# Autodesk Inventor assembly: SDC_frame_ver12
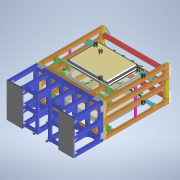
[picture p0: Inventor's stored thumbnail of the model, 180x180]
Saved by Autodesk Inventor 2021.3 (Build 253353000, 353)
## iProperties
Created: 2022-02
Part Number: SDC_frame_ver12
Document SubType Name: Assembly
Designer: kengo
Author: kengo
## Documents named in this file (13)
- C:\Users\kengo\Documents\frame_misumi_ver12\SDC_frame_ver12.iam
- C:\Users\kengo\Documents\frame_misumi_ver12\SDC_frame_arm_12.iam
- C:\Users\kengo\Documents\frame_misumi_ver12\SDC_frame_leg_12.iam
- C:\Users\kengo\Documents\frame_misumi_ver12\HBLFSDW8-90-SET_tuika.iam
- C:\Users\kengo\Documents\frame_misumi_ver12\JTAC-SET.iam
- C:\Users\kengo\Documents\frame_misumi_ver12\upper-stage\SDC345_up_stage.iam
- C:\Users\kengo\Documents\frame_misumi_ver12\upper-stage\SDC345_up_stage_mirror.iam
- C:\Users\kengo\Documents\frame_misumi_ver12\stage\SDC345_down_stage.iam
- C:\Users\kengo\Documents\frame_misumi_ver12\stage\SDC345_down_stage_mirror.iam
- C:\Users\kengo\Documents\frame_misumi_ver12\Anker\foot\SDC_foot_ver9.iam
- C:\Users\kengo\Documents\frame_misumi_ver12\IBolt\Ibolt_set.iam
- C:\Users\kengo\Documents\frame_misumi_ver12\SDC13301330\SDC_E70_assembly.iam
- C:\Users\kengo\Documents\frame_misumi_ver12\SDCsmallY\SDC_smallY.ipt
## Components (39 placed, 12 different names)
1. SDC_frame_arm_12:1 [sub-assembly] — メイト:1, フラッシュ:1, フラッシュ:2, メイト:29, メイト:31, メイト:33, メイト:35, メイト:37, メイト:39, メイト:41, メイト:43, メイト:44, フラッシュ:55, メイト:45, フラッシュ:57, メイト:46, フラッシュ:59, メイト:47, フラッシュ:61, メイト:48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
2. SDC_frame_leg_12:1 [sub-assembly] — メイト:1, フラッシュ:1, フラッシュ:2, メイト:28, フラッシュ:46, メイト:30, フラッシュ:47, メイト:32, フラッシュ:48, メイト:34, フラッシュ:49, メイト:36, フラッシュ:50, メイト:38, フラッシュ:51, メイト:40, フラッシュ:52, メイト:42, フラッシュ:53, フラッシュ:54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
3. HBLFSDW8-90-SET_tuika:1 [sub-assembly] — メイト:34, メイト:35, フラッシュ:49
4. HBLFSDW8-90-SET_tuika:2 [sub-assembly] — メイト:30, メイト:31, フラッシュ:47
5. HBLFSDW8-90-SET_tuika:3 [sub-assembly] — メイト:28, メイト:29, フラッシュ:46
6. HBLFSDW8-90-SET_tuika:4 [sub-assembly] — メイト:32, メイト:33, フラッシュ:48
7. HBLFSDW8-90-SET_tuika:5 [sub-assembly] — メイト:40, メイト:41, フラッシュ:52
8. HBLFSDW8-90-SET_tuika:6 [sub-assembly] — メイト:42, メイト:43, フラッシュ:53
9. HBLFSDW8-90-SET_tuika:7 [sub-assembly] — メイト:36, メイト:37, フラッシュ:50
10. HBLFSDW8-90-SET_tuika:8 [sub-assembly] — メイト:38, メイト:39, フラッシュ:51
11. JTAC-SET:1 [sub-assembly] — メイト:46, フラッシュ:58, フラッシュ:59
12. JTAC-SET:2 [sub-assembly] — メイト:47, フラッシュ:60, フラッシュ:61
13. JTAC-SET:3 [sub-assembly] — メイト:45, フラッシュ:56, フラッシュ:57
14. JTAC-SET:4 [sub-assembly] — メイト:44, フラッシュ:54, フラッシュ:55
15. JTAC-SET:5 [sub-assembly] — メイト:51, フラッシュ:68, フラッシュ:69
16. JTAC-SET:6 [sub-assembly] — メイト:50, フラッシュ:66, フラッシュ:67
17. JTAC-SET:7 [sub-assembly] — メイト:49, フラッシュ:64, フラッシュ:65
18. JTAC-SET:8 [sub-assembly] — メイト:48, フラッシュ:62, フラッシュ:63
19. SDC345_up_stage:1 [sub-assembly] — メイト:54, フラッシュ:74, フラッシュ:75
20. SDC345_up_stage:2 [sub-assembly] — メイト:53, フラッシュ:72, フラッシュ:73
21. SDC345_up_stage:3 [sub-assembly] — メイト:52, フラッシュ:70, フラッシュ:71
22. SDC345_up_stage_mirror:1 [sub-assembly] — メイト:56, フラッシュ:78, フラッシュ:79
23. SDC345_up_stage_mirror:2 [sub-assembly] — メイト:55, フラッシュ:76, フラッシュ:77
24. SDC345_up_stage_mirror:3 [sub-assembly] — メイト:57, フラッシュ:80, フラッシュ:81
25. SDC345_down_stage:1 [sub-assembly] — メイト:58, フラッシュ:82, フラッシュ:83, メイト:74
26. SDC345_down_stage:2 [sub-assembly] — メイト:59, フラッシュ:84, フラッシュ:85
27. SDC345_down_stage:3 [sub-assembly] — メイト:60, フラッシュ:86, フラッシュ:87
28. SDC345_down_stage_mirror:1 [sub-assembly] — メイト:61, フラッシュ:88, フラッシュ:89
29. SDC345_down_stage_mirror:2 [sub-assembly] — メイト:63, フラッシュ:92, フラッシュ:93, メイト:72
30. SDC345_down_stage_mirror:3 [sub-assembly] — メイト:62, フラッシュ:90, フラッシュ:91, メイト:70
31. SDC_foot_ver9:1 [sub-assembly] — メイト:64, フラッシュ:94, フラッシュ:95
32. SDC_foot_ver9:2 [sub-assembly] — メイト:65, フラッシュ:96, フラッシュ:97
33. Ibolt_set:1 [sub-assembly] — メイト:68, フラッシュ:102, フラッシュ:103
34. Ibolt_set:2 [sub-assembly] — メイト:66, フラッシュ:98, フラッシュ:99
35. Ibolt_set:3 [sub-assembly] — メイト:67, フラッシュ:100, フラッシュ:101
36. Ibolt_set:4 [sub-assembly] — メイト:69, フラッシュ:104, フラッシュ:105
37. SDC_E70_assembly:1 [sub-assembly] — メイト:70, フラッシュ:106, メイト:71
38. SDC_E70_assembly:2 [sub-assembly] — メイト:72, フラッシュ:107, メイト:73
39. SDC_smallY:1 — メイト:74, フラッシュ:108, メイト:75
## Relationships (114: Flush 65, Mate 49)
- メイト:1 [Mate]: SDC_frame_arm_12:1 ↔ SDC_frame_leg_12:1
- フラッシュ:1 [Flush]: SDC_frame_arm_12:1 ↔ SDC_frame_leg_12:1
- フラッシュ:2 [Flush]: SDC_frame_arm_12:1 ↔ SDC_frame_leg_12:1
- メイト:28 [Mate]: SDC_frame_leg_12:1 ↔ HBLFSDW8-90-SET_tuika:3
- メイト:29 [Mate]: SDC_frame_arm_12:1 ↔ HBLFSDW8-90-SET_tuika:3
- フラッシュ:46 [Flush]: SDC_frame_leg_12:1 ↔ HBLFSDW8-90-SET_tuika:3
- メイト:30 [Mate]: SDC_frame_leg_12:1 ↔ HBLFSDW8-90-SET_tuika:2
- メイト:31 [Mate]: SDC_frame_arm_12:1 ↔ HBLFSDW8-90-SET_tuika:2
- フラッシュ:47 [Flush]: SDC_frame_leg_12:1 ↔ HBLFSDW8-90-SET_tuika:2
- メイト:32 [Mate]: SDC_frame_leg_12:1 ↔ HBLFSDW8-90-SET_tuika:4
- メイト:33 [Mate]: SDC_frame_arm_12:1 ↔ HBLFSDW8-90-SET_tuika:4
- フラッシュ:48 [Flush]: SDC_frame_leg_12:1 ↔ HBLFSDW8-90-SET_tuika:4
- メイト:34 [Mate]: SDC_frame_leg_12:1 ↔ HBLFSDW8-90-SET_tuika:1
- メイト:35 [Mate]: SDC_frame_arm_12:1 ↔ HBLFSDW8-90-SET_tuika:1
- フラッシュ:49 [Flush]: SDC_frame_leg_12:1 ↔ HBLFSDW8-90-SET_tuika:1
- メイト:36 [Mate]: SDC_frame_leg_12:1 ↔ HBLFSDW8-90-SET_tuika:7
- メイト:37 [Mate]: SDC_frame_arm_12:1 ↔ HBLFSDW8-90-SET_tuika:7
- フラッシュ:50 [Flush]: SDC_frame_leg_12:1 ↔ HBLFSDW8-90-SET_tuika:7
- メイト:38 [Mate]: SDC_frame_leg_12:1 ↔ HBLFSDW8-90-SET_tuika:8
- メイト:39 [Mate]: SDC_frame_arm_12:1 ↔ HBLFSDW8-90-SET_tuika:8
- フラッシュ:51 [Flush]: SDC_frame_leg_12:1 ↔ HBLFSDW8-90-SET_tuika:8
- メイト:40 [Mate]: SDC_frame_leg_12:1 ↔ HBLFSDW8-90-SET_tuika:5
- メイト:41 [Mate]: SDC_frame_arm_12:1 ↔ HBLFSDW8-90-SET_tuika:5
- フラッシュ:52 [Flush]: SDC_frame_leg_12:1 ↔ HBLFSDW8-90-SET_tuika:5
- メイト:42 [Mate]: SDC_frame_leg_12:1 ↔ HBLFSDW8-90-SET_tuika:6
- メイト:43 [Mate]: SDC_frame_arm_12:1 ↔ HBLFSDW8-90-SET_tuika:6
- フラッシュ:53 [Flush]: SDC_frame_leg_12:1 ↔ HBLFSDW8-90-SET_tuika:6
- メイト:44 [Mate]: SDC_frame_arm_12:1 ↔ JTAC-SET:4
- フラッシュ:54 [Flush]: SDC_frame_leg_12:1 ↔ JTAC-SET:4
- フラッシュ:55 [Flush]: SDC_frame_arm_12:1 ↔ JTAC-SET:4
- メイト:45 [Mate]: SDC_frame_arm_12:1 ↔ JTAC-SET:3
- フラッシュ:56 [Flush]: SDC_frame_leg_12:1 ↔ JTAC-SET:3
- フラッシュ:57 [Flush]: SDC_frame_arm_12:1 ↔ JTAC-SET:3
- メイト:46 [Mate]: SDC_frame_arm_12:1 ↔ JTAC-SET:1
- フラッシュ:58 [Flush]: SDC_frame_leg_12:1 ↔ JTAC-SET:1
- フラッシュ:59 [Flush]: SDC_frame_arm_12:1 ↔ JTAC-SET:1
- メイト:47 [Mate]: SDC_frame_arm_12:1 ↔ JTAC-SET:2
- フラッシュ:60 [Flush]: SDC_frame_leg_12:1 ↔ JTAC-SET:2
- フラッシュ:61 [Flush]: SDC_frame_arm_12:1 ↔ JTAC-SET:2
- メイト:48 [Mate]: SDC_frame_arm_12:1 ↔ JTAC-SET:8
- フラッシュ:62 [Flush]: SDC_frame_leg_12:1 ↔ JTAC-SET:8
- フラッシュ:63 [Flush]: SDC_frame_leg_12:1 ↔ JTAC-SET:8
- メイト:49 [Mate]: SDC_frame_arm_12:1 ↔ JTAC-SET:7
- フラッシュ:64 [Flush]: SDC_frame_leg_12:1 ↔ JTAC-SET:7
- フラッシュ:65 [Flush]: SDC_frame_leg_12:1 ↔ JTAC-SET:7
- メイト:50 [Mate]: SDC_frame_arm_12:1 ↔ JTAC-SET:6
- フラッシュ:66 [Flush]: SDC_frame_leg_12:1 ↔ JTAC-SET:6
- フラッシュ:67 [Flush]: SDC_frame_leg_12:1 ↔ JTAC-SET:6
- メイト:51 [Mate]: SDC_frame_arm_12:1 ↔ JTAC-SET:5
- フラッシュ:68 [Flush]: SDC_frame_leg_12:1 ↔ JTAC-SET:5
- フラッシュ:69 [Flush]: SDC_frame_leg_12:1 ↔ JTAC-SET:5
- メイト:52 [Mate]: SDC_frame_arm_12:1 ↔ SDC345_up_stage:3
- フラッシュ:70 [Flush]: SDC_frame_arm_12:1 ↔ SDC345_up_stage:3
- フラッシュ:71 [Flush]: SDC_frame_arm_12:1 ↔ SDC345_up_stage:3
- メイト:53 [Mate]: SDC_frame_arm_12:1 ↔ SDC345_up_stage:2
- フラッシュ:72 [Flush]: SDC_frame_arm_12:1 ↔ SDC345_up_stage:2
- フラッシュ:73 [Flush]: SDC_frame_arm_12:1 ↔ SDC345_up_stage:2
- メイト:54 [Mate]: SDC_frame_arm_12:1 ↔ SDC345_up_stage:1
- フラッシュ:74 [Flush]: SDC_frame_arm_12:1 ↔ SDC345_up_stage:1
- フラッシュ:75 [Flush]: SDC_frame_arm_12:1 ↔ SDC345_up_stage:1
- メイト:55 [Mate]: SDC_frame_arm_12:1 ↔ SDC345_up_stage_mirror:2
- フラッシュ:76 [Flush]: SDC_frame_arm_12:1 ↔ SDC345_up_stage_mirror:2
- フラッシュ:77 [Flush]: SDC_frame_arm_12:1 ↔ SDC345_up_stage_mirror:2
- メイト:56 [Mate]: SDC_frame_arm_12:1 ↔ SDC345_up_stage_mirror:1
- フラッシュ:78 [Flush]: SDC_frame_arm_12:1 ↔ SDC345_up_stage_mirror:1
- フラッシュ:79 [Flush]: SDC_frame_arm_12:1 ↔ SDC345_up_stage_mirror:1
- メイト:57 [Mate]: SDC_frame_arm_12:1 ↔ SDC345_up_stage_mirror:3
- フラッシュ:80 [Flush]: SDC_frame_arm_12:1 ↔ SDC345_up_stage_mirror:3
- フラッシュ:81 [Flush]: SDC_frame_arm_12:1 ↔ SDC345_up_stage_mirror:3
- メイト:58 [Mate]: SDC_frame_arm_12:1 ↔ SDC345_down_stage:1
- フラッシュ:82 [Flush]: SDC_frame_arm_12:1 ↔ SDC345_down_stage:1
- フラッシュ:83 [Flush]: SDC_frame_arm_12:1 ↔ SDC345_down_stage:1
- メイト:59 [Mate]: SDC_frame_arm_12:1 ↔ SDC345_down_stage:2
- フラッシュ:84 [Flush]: SDC_frame_arm_12:1 ↔ SDC345_down_stage:2
- フラッシュ:85 [Flush]: SDC_frame_arm_12:1 ↔ SDC345_down_stage:2
- メイト:60 [Mate]: SDC_frame_arm_12:1 ↔ SDC345_down_stage:3
- フラッシュ:86 [Flush]: SDC_frame_arm_12:1 ↔ SDC345_down_stage:3
- フラッシュ:87 [Flush]: SDC_frame_arm_12:1 ↔ SDC345_down_stage:3
- メイト:61 [Mate]: SDC_frame_arm_12:1 ↔ SDC345_down_stage_mirror:1
- フラッシュ:88 [Flush]: SDC_frame_arm_12:1 ↔ SDC345_down_stage_mirror:1
- フラッシュ:89 [Flush]: SDC_frame_arm_12:1 ↔ SDC345_down_stage_mirror:1
- メイト:62 [Mate]: SDC_frame_arm_12:1 ↔ SDC345_down_stage_mirror:3
- フラッシュ:90 [Flush]: SDC_frame_arm_12:1 ↔ SDC345_down_stage_mirror:3
- フラッシュ:91 [Flush]: SDC_frame_arm_12:1 ↔ SDC345_down_stage_mirror:3
- メイト:63 [Mate]: SDC_frame_arm_12:1 ↔ SDC345_down_stage_mirror:2
- フラッシュ:92 [Flush]: SDC_frame_arm_12:1 ↔ SDC345_down_stage_mirror:2
- フラッシュ:93 [Flush]: SDC_frame_arm_12:1 ↔ SDC345_down_stage_mirror:2
- メイト:64 [Mate]: SDC_frame_leg_12:1 ↔ SDC_foot_ver9:1
- フラッシュ:94 [Flush]: SDC_frame_leg_12:1 ↔ SDC_foot_ver9:1
- フラッシュ:95 [Flush]: SDC_frame_leg_12:1 ↔ SDC_foot_ver9:1
- メイト:65 [Mate]: SDC_frame_leg_12:1 ↔ SDC_foot_ver9:2
- フラッシュ:96 [Flush]: SDC_frame_leg_12:1 ↔ SDC_foot_ver9:2
- フラッシュ:97 [Flush]: SDC_frame_leg_12:1 ↔ SDC_foot_ver9:2
- メイト:66 [Mate]: SDC_frame_arm_12:1 ↔ Ibolt_set:2
- フラッシュ:98 [Flush]: SDC_frame_arm_12:1 ↔ Ibolt_set:2
- フラッシュ:99 [Flush]: SDC_frame_arm_12:1 ↔ Ibolt_set:2
- メイト:67 [Mate]: SDC_frame_arm_12:1 ↔ Ibolt_set:3
- フラッシュ:100 [Flush]: SDC_frame_arm_12:1 ↔ Ibolt_set:3
- フラッシュ:101 [Flush]: SDC_frame_arm_12:1 ↔ Ibolt_set:3
- メイト:68 [Mate]: SDC_frame_arm_12:1 ↔ Ibolt_set:1
- フラッシュ:102 [Flush]: SDC_frame_arm_12:1 ↔ Ibolt_set:1
- フラッシュ:103 [Flush]: SDC_frame_arm_12:1 ↔ Ibolt_set:1
- メイト:69 [Mate]: SDC_frame_arm_12:1 ↔ Ibolt_set:4
- フラッシュ:104 [Flush]: SDC_frame_arm_12:1 ↔ Ibolt_set:4
- フラッシュ:105 [Flush]: SDC_frame_arm_12:1 ↔ Ibolt_set:4
- メイト:70 [Mate]: SDC345_down_stage_mirror:3 ↔ SDC_E70_assembly:1
- フラッシュ:106 [Flush]: SDC_frame_arm_12:1 ↔ SDC_E70_assembly:1
- メイト:71 [Mate]: SDC_frame_arm_12:1 ↔ SDC_E70_assembly:1
- メイト:72 [Mate]: SDC345_down_stage_mirror:2 ↔ SDC_E70_assembly:2
- フラッシュ:107 [Flush]: SDC_frame_arm_12:1 ↔ SDC_E70_assembly:2
- メイト:73 [Mate]: SDC_frame_arm_12:1 ↔ SDC_E70_assembly:2
- メイト:74 [Mate]: SDC345_down_stage:1 ↔ SDC_smallY:1
- フラッシュ:108 [Flush]: SDC_frame_arm_12:1 ↔ SDC_smallY:1
- メイト:75 [Mate]: SDC_frame_arm_12:1 ↔ SDC_smallY:1
